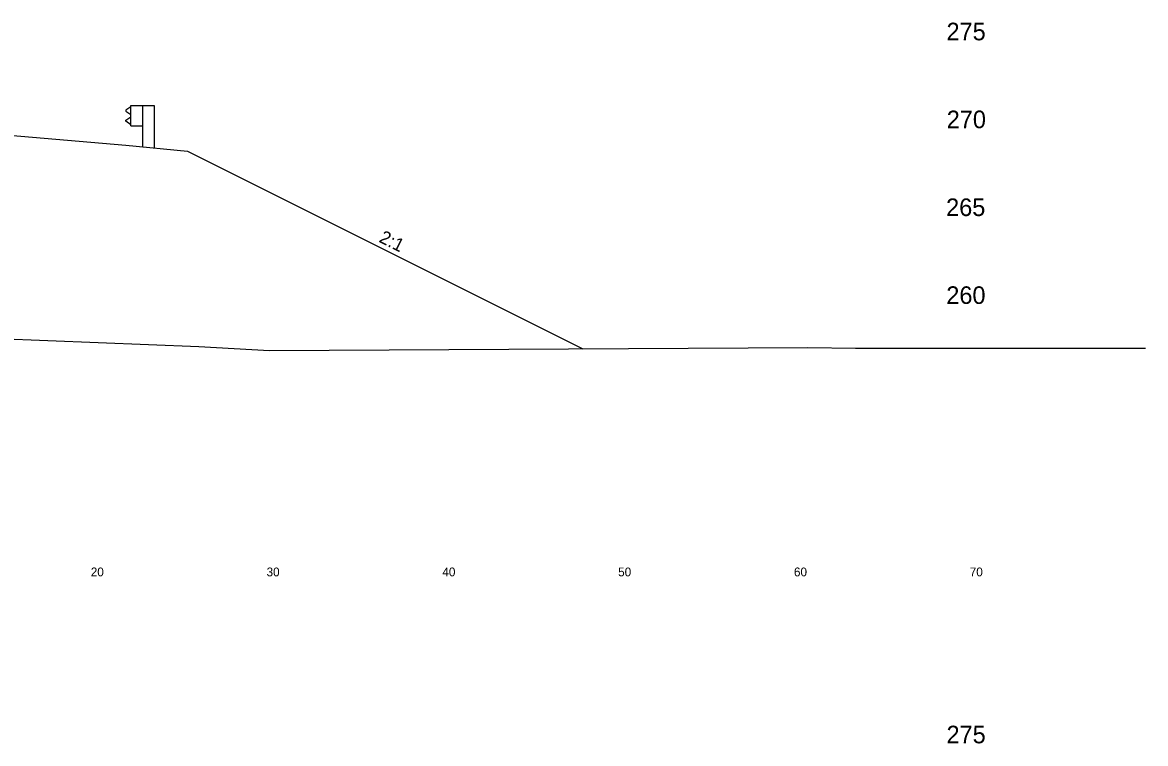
# Model space of a CAD drawing. Extents: x 1000 to 1162, y 999 to 8520.
# Drawn here: x 1096.1 to 1160, y 4715 to 4756 of the extents above; entities that cross this region are included whole.
import ezdxf

# ---------------------------------------------------------------- set-up
doc = ezdxf.new("R2010")
doc.units = 0
for name, color, linetype in [('Level 11', 7, 'Continuous'), ('Level 24', 7, 'Continuous'), ('Level 32', 7, 'Continuous'), ('Level 56', 7, 'Continuous'), ('Level 6', 7, 'Continuous'), ('Level 60', 7, 'Continuous'), ('Level 7', 7, 'Continuous')]:
    doc.layers.add(name, color=color, linetype=linetype)

msp = doc.modelspace()

# ---------------------------------------------------------------- linework, layer by layer
at = {"layer": 'Level 24'}
for p, q in [((1102.271, 4751.219), (1102, 4751.019)), ((1102.271, 4750.125), (1102.271, 4751.292)), ((1102.271, 4751.292), (1102.937, 4751.292)), ((1102.937, 4751.292), (1102.937, 4748.949)), ((1102.937, 4751.292), (1103.603, 4751.292)), ((1103.603, 4751.292), (1103.603, 4748.882)), ((1102, 4751.019), (1102, 4750.969)), ((1102, 4750.969), (1102.271, 4750.769)), ((1102, 4750.448), (1102.271, 4750.648)), ((1102, 4750.398), (1102, 4750.448)), ((1102.271, 4750.198), (1102, 4750.398)), ((1102.271, 4750.125), (1102.938, 4750.125))]:
    msp.add_line(p, q, dxfattribs=at)
at = {"layer": 'Level 6'}
for p, q in [((1094, 4749.709), (1102, 4749.042)), ((1102, 4749.042), (1105.5, 4748.692))]:
    msp.add_line(p, q, dxfattribs=at)
at = {"layer": 'Level 60'}
for p, q in [((1080, 4738.619), (1106.153, 4737.573)), ((1106.153, 4737.573), (1110.166, 4737.343)), ((1110.166, 4737.343), (1140.784, 4737.528)), ((1140.784, 4737.528), (1143.51, 4737.478)), ((1143.51, 4737.478), (1160, 4737.477))]:
    msp.add_line(p, q, dxfattribs=at)
at = {"layer": 'Level 7'}
msp.add_line((1105.5, 4748.692), (1127.983, 4737.451), dxfattribs=at)

# ---------------------------------------------------------------- texts
at = {"layer": 'Level 11'}
for s, p in [(' 275', (1148.307, 4755)), (' 270', (1148.319, 4750)), (' 265', (1148.284, 4745)), (' 260', (1148.295, 4740)), (' 275', (1148.307, 4715))]:
    msp.add_text(s, height=1, dxfattribs=at).set_placement(p)
at = {"layer": 'Level 32'}
msp.add_text('2:1', height=0.75, rotation=333.43495, dxfattribs=at).set_placement((1116.346, 4743.549))
at = {"layer": 'Level 56'}
for s, p in [('20', (1100, 4724.5)), ('30', (1110, 4724.5)), ('40', (1120, 4724.5)), ('50', (1130, 4724.5)), ('60', (1140, 4724.5)), ('70', (1150, 4724.5))]:
    msp.add_text(s, height=0.5, dxfattribs=at).set_placement(p)

doc.saveas('drawing.dxf')
